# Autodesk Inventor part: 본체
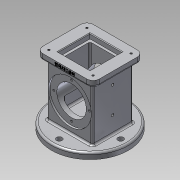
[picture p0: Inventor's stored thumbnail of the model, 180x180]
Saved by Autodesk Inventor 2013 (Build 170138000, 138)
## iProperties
Created: 2018-10
Part Number: 본체
Material: 알루미늄 6061
Document SubType Name: Modeling
Designer: hana-cad36
Density: 2.40731 g/cm^3
Mass: 877.848 g
Surface Area: 743.905 cm^2
Volume: 364.659 cm^3
Author: hana-cad36
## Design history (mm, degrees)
sketch "스케치1"
  geometry: C1 r 62.5 at (0, 0); 1 further point
  constraints: 1 centre point, 1 coincident
  dimensions: "d0" = 62.5 radius of C1
extrude "돌출1" new body sketch "스케치1" distance "d1" = 10; taper "d2" = 0 deg
node "작업 평면1"
sketch "스케치3"
  geometry: L1 (46, -41)-(-46, -41); L2 (-46, -41)-(-46, 41); L3 (-46, 41)-(46, 41); L4 (46, 41)-(46, -41); L5 (46, -41)-(-46, 41); L6 (-46, -41)-(46, 41); 1 further point
  constraints: 12 end point, 2 midpoint, 2 parallel, 1 horizontal, 1 perpendicular
  dimensions: "d8" = 92 distance of L2.end L3.end; "d10" = 82 distance of L3.end L1.start
extrude "돌출2" join sketch "스케치3" distance "d11" = 10; taper "d12" = 0 deg
sketch "스케치4"
  geometry: L1 (37, -33)-(-37, -33); L2 (-37, -33)-(-37, 33); L3 (-37, 33)-(37, 33); L4 (37, 33)-(37, -33); L5 (37, -33)-(-37, 33); L6 (-37, -33)-(37, 33); C1 r 62.5 at (0, 0) reference
  constraints: 12 end point, 2 midpoint, 2 parallel, 1 horizontal, 1 perpendicular
  dimensions: "d13" = 74 distance of L2.end L3.end; "d15" = 66 distance of L3.end L1.start
extrude "돌출3" join sketch "스케치4" stored distance "d16" = 10; taper "d17" = 0 deg
node "작업 평면2"
node "작업 평면3"
sketch "스케치7"
  geometry: L1 (62.5, 10)-(62.5, 0) reference; L2 (62.5, 0)-(-62.5, 0) reference; L3 (-62.5, 0)-(-62.5, 10) reference; L4 (-62.5, 10)-(-33, 10) reference; L5 (-33, 10)-(-33, 98) reference; L6 (-33, 98)-(-41, 98) reference; L7 (-41, 98)-(-41, 108) reference; L8 (-41, 108)-(41, 108) reference; L9 (41, 108)-(41, 98) reference; L10 (41, 98)-(33, 98) reference; L11 (33, 98)-(33, 10) reference; L12 (33, 10)-(62.5, 10) reference; L13 (-33, 54)-(33, 54); L14 (-33, 89)-(-30, 89); L15 (-30, 89)-(-30, 78); L16 (-30, 78)-(30, 78); L17 (30, 78)-(30, 89); L18 (30, 89)-(33, 89); 3 further points
  constraints: 12 end point, 4 midpoint, 3 parallel, 2 perpendicular, 2 point on line, 1 collinear, 1 vertical alignment
  dimensions: "d32" = 70 diameter of L18 L13; "d34" = 3 distance of L17.end L18.end; "d35" = 48 diameter of L16 L13
revolve "회전1" sketch "스케치7" stored, may be unused: angle "d36" = 90 deg
sketch "스케치8"
  geometry: L1 (26, -26)-(-26, -26); L2 (-26, -26)-(-26, 26); L3 (-26, 26)-(26, 26); L4 (26, 26)-(26, -26); L5 (26, -26)-(-26, 26); L6 (-26, -26)-(26, 26); 1 further point
  constraints: 12 end point, 2 midpoint, 2 parallel, 2 perpendicular, 1 horizontal
  dimensions: "d37" = 52 distance of L2.end L3.end
extrude "돌출4" cut sketch "스케치8" distance "d39" = 8; taper "d40" = 0 deg
sketch "스케치9"
  geometry: L1 (22, -22)-(-22, -22); L2 (-22, -22)-(-22, 22); L3 (-22, 22)-(22, 22); L4 (22, 22)-(22, -22); L5 (22, -22)-(-22, 22); L6 (-22, -22)-(22, 22); 1 further point
  constraints: 12 end point, 2 midpoint, 2 parallel, 2 perpendicular, 1 horizontal
  dimensions: "d41" = 44 distance of L2.end L3.end
extrude "돌출5" cut sketch "스케치9" distance "d43" = 74; taper "d44" = 0 deg
sketch "스케치10"
  geometry: C1 r 62.5 at (0, 0) reference; 1 further point
  constraints: 1 vertical alignment
  dimensions: "d45" = 50 distance of point (0, 50) C1.centre
hole "구멍1" sketch "스케치10" at (0, 50) diameter "d46" = 9; stored, may be unused: countersink angle "d50" = 90 deg, drill point angle "d52" = 118 deg; dims "d47" = 6, "d48" = 4, "d49" = 2, "d51" = 8
sketch "스케치11"
  geometry: C1 r 35 at (0, 0) reference; 2 further points
  constraints: 1 vertical alignment
  dimensions: "d56" = 29 distance of point (0, 29) C1.centre
hole "구멍2" sketch "스케치11" at (0, 29) diameter "d57" = 3.242; stored, may be unused: countersink angle "d61" = 90 deg, drill point angle "d63" = 118 deg; dims "d58" = 4, "d59" = 4, "d60" = 2, "d62" = 6
sketch "스케치12"
  geometry: L1 (0, 66)-(0, 0) reference; L2 (10, -29.5)-(10, 95.5) reference; 4 further points
  constraints: 2 horizontal alignment, 1 midpoint
  dimensions: "d67" = 37 distance from line of point (-27, 33) L2; "d68" = 43 distance of point (-70, 33) point (-27, 33)
hole "구멍3" sketch "스케치12" at (-70, 33), (-27, 33) diameter "d69" = 4.134; stored, may be unused: countersink angle "d73" = 90 deg, drill point angle "d75" = 118 deg; dims "d70" = 43 (= d68), "d71" = 4, "d72" = 2, "d74" = 43 (= d68)
node "작업 평면4"
sketch "스케치14"
  geometry: L1 (37, 39.067)-(22, 39.067) reference; L2 (22, 63.592)-(22, 77.933) reference; L3 (22, 77.933)-(37, 77.933) reference; L4 (37, 77.933)-(37, 39.067) reference; L5 (26, 100)-(26, 108) reference; L6 (26, 108)-(46, 108) reference; L7 (46, 108)-(46, 98) reference; L8 (46, 98)-(37, 98) reference; L9 (37, 98)-(37, 82.067) reference; L10 (37, 82.067)-(22, 82.067) reference; L11 (22, 82.067)-(22, 100) reference; L12 (22, 100)-(26, 100) reference; L13 (-37, 10)-(-37, 98) reference; L14 (-37, 98)-(-46, 98) reference; L15 (-46, 98)-(-46, 108) reference; L16 (-46, 108)-(-26, 108) reference; L17 (-26, 108)-(-26, 100) reference; L18 (-26, 100)-(-22, 100) reference; L19 (-22, 100)-(-22, 63.592) reference; L20 (22, 34.933)-(37, 34.933) reference; L21 (37, 34.933)-(37, 10) reference; L22 (37, 10)-(45.5, 10) reference; L23 (45.5, 10)-(45.5, 0) reference; L24 (45.5, 0)-(-45.5, 0) reference; L25 (-45.5, 0)-(-45.5, 10) reference; L26 (-45.5, 10)-(-37, 10) reference; L27 (-62.5, 0)-(-62.5, 10) reference; L28 (-62.5, 10)-(-54.5, 10) reference; L29 (-54.5, 10)-(-54.5, 0) reference; L30 (-54.5, 0)-(-62.5, 0) reference; L31 (62.5, 10)-(62.5, 0) reference; L32 (62.5, 0)-(54.5, 0) reference; L33 (54.5, 0)-(54.5, 10) reference; L34 (54.5, 10)-(62.5, 10) reference; L35 (0, 0)-(0, 18); L36 (0, 18)-(-24.826, 18); L37 (-24.826, 18)-(-28, 0); L38 (22, 39.067)-(22, 44.408) reference; L39 (-22, 44.408)-(-22, 26) reference; L40 (-22, 26)-(22, 26) reference; L41 (22, 26)-(22, 34.933) reference; A1 r 24 centre (0, 54) between (22, 44.408) and (22, 63.592) reference; A2 r 24 centre (0, 54) between (-22, 63.592) and (-22, 44.408) reference; 1 further point
  constraints: 6 end point, 2 perpendicular, 1 midpoint, 1 point on line, 1 vertical alignment
  dimensions: "d80" = 18 distance between parallel lines of L36 L24; "d81" = 80 deg angle of L37 L24; "d82" = 56 diameter of L37.end L35
revolve "회전2" sketch "스케치14" stored, may be unused: angle "d83" = 90 deg
fillet "모깎기1" dims "d84" = 10
sketch "스케치16"
  geometry: A1 r 10 centre (-36, 31) between (-36, 41) and (-46, 31) reference; A2 r 10 centre (-36, -31) between (-46, -31) and (-36, -41) reference; A3 r 10 centre (36, -31) between (36, -41) and (46, -31) reference; A4 r 10 centre (36, 31) between (46, 31) and (36, 41) reference; 1 further point
hole "구멍4" sketch "스케치16" at (-36, 31), (-36, -31), (36, -31), (36, 31) diameter "d85" = 3.242; stored, may be unused: countersink angle "d89" = 90 deg, drill point angle "d91" = 118 deg; dims "d86" = 4, "d87" = 4, "d88" = 2, "d90" = 6
sketch "스케치17"
  geometry: L1 (0, 10)-(72, 10) reference; L2 (-10, 10)-(-10, 0) reference; 2 further points
  constraints: 1 other
  dimensions: "d92" = 46 distance from line of point (36, 6) L2; "d93" = 4 distance from line of L1 point (36, 6)
feature "엠보싱1" sketch "스케치17" dims "d94" = 0.5, "d95" = 0
chamfer "모따기1" distance "d96" = 1; stored, may be unused: second distance "d97" = 2, angle "d98" = 45 deg
fillet "모깎기2" dims "d99" = 3
fillet "모깎기3" dims "d100" = 3
fillet "모깎기4" dims "d101" = 3
fillet "모깎기5" dims "d102" = 3
fillet "모깎기6" dims "d103" = 3
fillet "모깎기7" dims "d104" = 3
fillet "모깎기8" dims "d105" = 3
fillet "모깎기9" dims "d106" = 3
fillet "모깎기10" dims "d107" = 3
node "솔리드1"
pattern_circular "원형 패턴1" dims angle "d54" = 360 deg
pattern_circular "원형 패턴2" dims angle "d65" = 360 deg
mirror "대칭1"
node "절단 모서리 투영2"
node "절단 모서리 투영3"
other parameters: "d7" = 98, "d22" = 90 deg, "d31" = 0, "d77" = 90 deg
